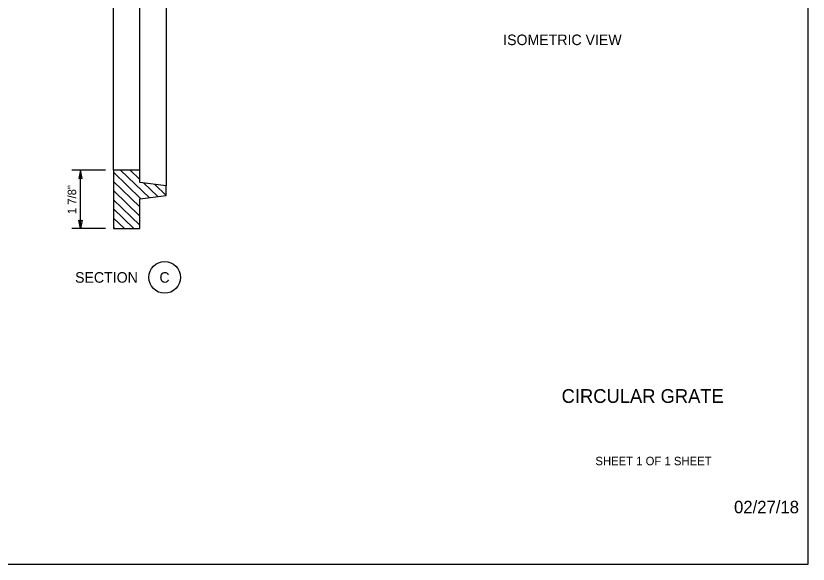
# Model space of a CAD drawing. Extents: x 99862 to 103151, y 100000 to 102076.
# Drawn here: x 101651 to 103151, y 100000 to 101038 of the extents above; entities that cross this region are included whole.
import ezdxf

# ---------------------------------------------------------------- set-up
doc = ezdxf.new("R2010")
doc.units = 0
for name, color, linetype in [('Level 1', 7, 'Continuous'), ('Level 12', 7, 'Continuous'), ('Level 15', 7, 'Continuous'), ('Level 18', 7, 'Continuous'), ('Level 20', 7, 'Continuous'), ('Level 62', 7, 'Continuous')]:
    doc.layers.add(name, color=color, linetype=linetype)

msp = doc.modelspace()

# ---------------------------------------------------------------- linework, layer by layer
at = {"layer": 'Level 1'}
msp.add_lwpolyline([(99862, 99999.5), (103151, 99999.5), (103151, 102075.5), (99862, 102075.5)], close=True, dxfattribs=at)
at = {"layer": 'Level 12'}
for p, q in [((101903.7, 100693.2), (101849.3, 100745.5)), ((101885.7, 100727.9), (101867.3, 100745.5)), ((101887.8, 100691.2), (101835.7, 100741.3)), ((101885.7, 100675.9), (101835.7, 100723.9)), ((101919.7, 100695.2), (101892.5, 100721.3)), ((101935.7, 100697.2), (101913.2, 100718.8)), ((101885.7, 100658.5), (101835.7, 100706.6)), ((101885.7, 100641.2), (101835.7, 100689.3)), ((101874.4, 100634.7), (101835.7, 100671.9)), ((101856.4, 100634.7), (101835.7, 100654.6)), ((101838.3, 100634.7), (101835.7, 100637.2))]:
    msp.add_line(p, q, dxfattribs=at)
at = {"layer": 'Level 15'}
for p, q in [((101820.7, 100745.5), (101757.2, 100745.5)), ((101773.2, 100634.7), (101773.2, 100745.5)), ((101820.7, 100634.7), (101757.2, 100634.7))]:
    msp.add_line(p, q, dxfattribs=at)
for points in [[(101773.2, 100745.5), (101770.1, 100729.8), (101773.2, 100730.5), (101776.3, 100729.8)], [(101773.2, 100634.7), (101770.1, 100650.4), (101773.2, 100649.7), (101776.3, 100650.4)]]:
    msp.add_lwpolyline(points, close=True, dxfattribs=at)
at = {"layer": 'Level 18'}
for p, q in [((101935.7, 101872.2), (101935.7, 100715.9)), ((101835.7, 100745.5), (101835.7, 101843.3)), ((101885.7, 100745.5), (101885.7, 101119.1))]:
    msp.add_line(p, q, dxfattribs=at)
msp.add_lwpolyline([(101885.7, 100722.2), (101885.7, 100745.5), (101835.7, 100745.5), (101835.7, 100634.7), (101885.7, 100634.7), (101885.7, 100690.9), (101935.7, 100697.2), (101935.7, 100715.9), (101885.7, 100722.2)], dxfattribs=at)
at = {"layer": 'Level 20'}
msp.add_circle((101932.7, 100542.3), 30, dxfattribs=at)

# ---------------------------------------------------------------- texts
at = {"layer": 'Level 15'}
msp.add_text('02/27/18', height=23.62, dxfattribs=at).set_placement((103010.7, 100095.8))
at = {"layer": 'Level 20'}
for s, p in [('ISOMETRIC VIEW', (102573.6, 100982.1)), ('SECTION', (101763.1, 100532.3)), ('C', (101922.8, 100532.3))]:
    msp.add_text(s, height=20, dxfattribs=at).set_placement(p)
msp.add_text('1 7/8"', height=16, rotation=90, dxfattribs=at).set_placement((101765.2, 100662))
at = {"layer": 'Level 62'}
for s, height, p in [('CIRCULAR GRATE', 26, (102684.2, 100304.8)), ('SHEET 1 OF 1 SHEET', 16, (102748.2, 100186.8))]:
    msp.add_text(s, height=height, dxfattribs=at).set_placement(p)

doc.saveas('drawing.dxf')
